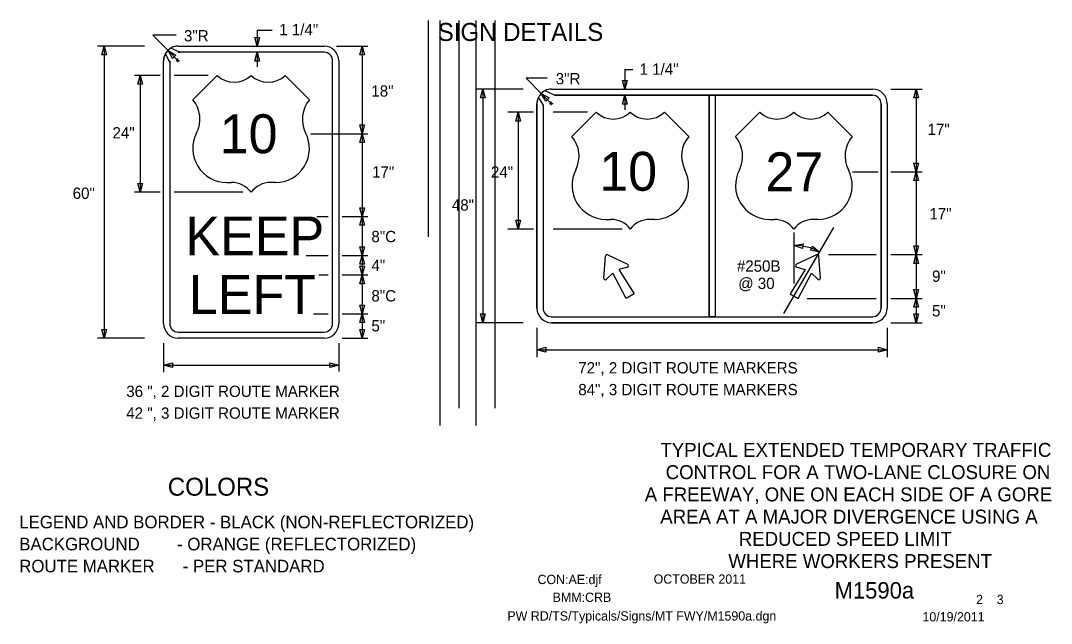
# Model space of a CAD drawing. Extents: x 16728 to 19504, y 5553 to 7079.
# Drawn here: x 17774 to 18463, y 5932 to 6334 of the extents above; entities that cross this region are included whole.
import ezdxf

# ---------------------------------------------------------------- set-up
doc = ezdxf.new("R2010")
doc.units = 0
for name, color, linetype in [('ALI_LEGAL_EX', 7, 'Continuous'), ('BORDER', 7, 'Continuous'), ('BORDER_SIGNAL_WO', 7, 'Continuous'), ('TRAFFIC_SIGNS_PR', 7, 'Continuous'), ('TYPICAL_EX', 7, 'Continuous'), ('TYPICAL_TEXT_DIMEN_PR', 7, 'Continuous')]:
    doc.layers.add(name, color=color, linetype=linetype)

msp = doc.modelspace()

# ---------------------------------------------------------------- linework, layer by layer
at = {"layer": 'ALI_LEGAL_EX'}
for p, q in [((18046.81, 6189.84), (18046.81, 6334.29)), ((18054.48, 6334.29), (18054.48, 6206.79)), ((18054.48, 6334.29), (18054.48, 6063.94)), ((18067.45, 6075.61), (18067.45, 6334.29)), ((18078.48, 6334.29), (18078.48, 6206.79)), ((18078.48, 6334.29), (18078.48, 6063.94)), ((18091.45, 6075.61), (18091.45, 6334.29))]:
    msp.add_line(p, q, dxfattribs=at)
at = {"layer": 'TRAFFIC_SIGNS_PR'}
for p, q in [((17879.58, 6317.25), (17977.08, 6317.25)), ((17872, 6313.63), (17870.99, 6312.12)), ((17871.02, 6312.05), (17873.89, 6306.01)), ((17880.78, 6313.18), (17874.69, 6315.93)), ((17977.08, 6313.18), (17879.58, 6313.18)), ((17869.83, 6132), (17869.83, 6307.5)), ((17873.89, 6307.5), (17873.89, 6132)), ((17982.77, 6132), (17982.77, 6307.5)), ((17986.83, 6307.5), (17986.83, 6132)), ((18120.27, 6282.81), (18123.41, 6277.76)), ((18131.06, 6284.5), (18124.82, 6287.51)), ((18129.1, 6288.55), (18343.6, 6288.55)), ((18129.1, 6288.55), (18343.6, 6288.55)), ((18131.04, 6284.49), (18234.32, 6284.49)), ((18343.6, 6284.49), (18131.04, 6284.49)), ((18234.32, 6284.49), (18234.32, 6136.61)), ((18238.38, 6284.49), (18238.38, 6136.61)), ((18238.38, 6284.49), (18343.6, 6284.49)), ((18119.35, 6278.8), (18119.35, 6142.3)), ((18119.35, 6142.3), (18119.35, 6278.8)), ((18123.41, 6277.75), (18123.41, 6142.3)), ((18123.41, 6277.75), (18123.41, 6142.3)), ((18349.29, 6278.8), (18349.29, 6233.05)), ((18349.29, 6142.3), (18349.29, 6278.8)), ((18353.35, 6278.8), (18353.35, 6142.3)), ((18353.35, 6278.8), (18353.35, 6142.3)), ((18349.29, 6233.05), (18349.29, 6142.3)), ((18163.95, 6162.41), (18165.1, 6177.12)), ((18166.62, 6177.99), (18179.93, 6171.63)), ((18306.08, 6177.99), (18292.77, 6171.63)), ((18308.75, 6162.41), (18307.6, 6177.12)), ((18129.1, 6136.61), (18343.6, 6136.61)), ((18129.1, 6132.55), (18343.6, 6132.55)), ((18343.6, 6132.55), (18129.1, 6132.55)), ((17879.58, 6126.31), (17977.08, 6126.31)), ((17977.08, 6122.25), (17879.58, 6122.25))]:
    msp.add_line(p, q, dxfattribs=at)
for points in [[(18131.04, 6284.49), (18131.03, 6284.49)], [(18123.41, 6277.76), (18123.41, 6277.75)], [(18179.77, 6169.66), (18174.04, 6168.09), (18184.26, 6151.92), (18178.86, 6148.8), (18169.97, 6165.74), (18165.74, 6161.57)], [(18292.93, 6169.66), (18298.66, 6168.09), (18288.44, 6151.92), (18293.84, 6148.8), (18302.73, 6165.74), (18306.96, 6161.57)]]:
    msp.add_lwpolyline(points, dxfattribs=at)
msp.add_lwpolyline([(18234.32, 6284.49), (18238.38, 6284.49), (18238.38, 6136.61), (18234.32, 6136.61)], close=True, dxfattribs=at)
for centre, radius, start, end in [((17879.58, 6307.5), 9.75, 90, 180), ((17878.99, 6309.67), 7.6, 85.58319, 124.53531), ((17977.08, 6307.5), 9.75, 0, 90), ((17876.86, 6308.09), 7.06, 145.86811, 184.82317), ((17880.18, 6317.61), 4.47, 262.2432, 277.7568), ((17977.08, 6307.5), 5.69, 0, 90), ((17868.43, 6306.75), 5.51, 352.24294, 7.75653), ((18125.48, 6279.5), 6.17, 147.60925, 186.56283), ((18129.1, 6278.8), 9.75, 90, 180), ((18129.1, 6278.8), 9.75, 90, 180), ((18128.42, 6281.98), 6.6, 84.11162, 123.06374), ((18130.04, 6291.67), 7.24, 277.81035, 278.05403), ((18343.6, 6278.8), 9.75, 0, 90), ((18343.6, 6278.8), 9.75, 0, 90), ((18343.6, 6278.8), 5.69, 0, 89.99421), ((18343.6, 6278.8), 5.69, 0, 90), ((18166.16, 6177.04), 1.06, 64.48226, 175.51774), ((18306.54, 6177.04), 1.06, 4.48226, 115.51774), ((18179.47, 6170.68), 1.06, 285.9885, 64.48226), ((18293.23, 6170.68), 1.06, 115.51774, 254.0115), ((18165.01, 6162.33), 1.06, 175.51775, 314.01151), ((18307.69, 6162.33), 1.06, 225.98849, 4.48225), ((18129.1, 6142.3), 9.75, 180, 270), ((18129.1, 6142.3), 9.75, 180, 270), ((18129.1, 6142.3), 5.69, 180, 270), ((18129.1, 6142.3), 5.69, 180, 270), ((18343.6, 6142.3), 9.75, 270, 0), ((18343.6, 6142.3), 5.69, 270, 0), ((18343.6, 6142.3), 9.75, 270, 0), ((18343.6, 6142.3), 5.69, 270, 0), ((17879.58, 6132), 9.75, 180, 270), ((17879.58, 6132), 5.69, 180, 270), ((17977.08, 6132), 5.69, 270, 0), ((17977.08, 6132), 9.75, 270, 0)]:
    msp.add_arc(centre, radius, start, end, dxfattribs=at)
at = {"layer": 'TYPICAL_EX'}
for p, q in [((17889.33, 6281.5), (17905.58, 6297.75)), ((17967.33, 6281.5), (17951.08, 6297.75)), ((18142.71, 6256.89), (18158.96, 6273.14)), ((18220.71, 6256.89), (18204.46, 6273.14)), ((18251.99, 6256.89), (18268.24, 6273.14)), ((18329.99, 6256.89), (18313.74, 6273.14)), ((17912.06, 6226.21), (17915.31, 6226.21)), ((17944.6, 6226.21), (17941.35, 6226.21)), ((18165.44, 6201.6), (18168.69, 6201.6)), ((18197.98, 6201.6), (18194.73, 6201.6)), ((18274.72, 6201.6), (18277.97, 6201.6)), ((18307.26, 6201.6), (18304.01, 6201.6))]:
    msp.add_line(p, q, dxfattribs=at)
for centre, radius, start, end in [((17916.95, 6309.58), 16.42, 226.14041, 313.85958), ((17939.7, 6309.59), 16.42, 226.14042, 313.85959), ((17873.93, 6268.49), 20.16, 333.09768, 40.19361), ((17982.73, 6268.49), 20.16, 139.80639, 206.90233), ((18170.34, 6284.97), 16.42, 226.14041, 313.85958), ((18193.09, 6284.97), 16.42, 226.14042, 313.85959), ((18279.62, 6284.97), 16.42, 226.14041, 313.85958), ((18302.36, 6284.97), 16.42, 226.14042, 313.85959), ((17912.1, 6248.93), 22.73, 152.6698, 269.90132), ((17944.56, 6248.93), 22.73, 270.09868, 27.3302), ((18127.31, 6243.88), 20.16, 333.09768, 40.19361), ((18236.11, 6243.88), 20.16, 139.80639, 206.90233), ((18236.59, 6243.88), 20.16, 333.09768, 40.19361), ((18345.39, 6243.88), 20.16, 139.80639, 206.90233), ((18165.48, 6224.32), 22.73, 152.6698, 269.90132), ((18197.94, 6224.32), 22.73, 270.09868, 27.3302), ((18274.76, 6224.32), 22.73, 152.6698, 269.90132), ((18307.22, 6224.32), 22.73, 270.09868, 27.3302), ((17915.35, 6209.93), 16.28, 37.1038, 90.13853), ((17941.31, 6209.93), 16.28, 89.86147, 142.8962), ((18168.73, 6185.32), 16.28, 37.1038, 90.13853), ((18194.69, 6185.32), 16.28, 89.86147, 142.8962), ((18278.01, 6185.32), 16.28, 37.1038, 90.13853), ((18303.97, 6185.32), 16.28, 89.86147, 142.8962)]:
    msp.add_arc(centre, radius, start, end, dxfattribs=at)
at = {"layer": 'TYPICAL_TEXT_DIMEN_PR'}
for p, q in [((17878.2, 6324.53), (17862.54, 6324.53)), ((17862.54, 6324.53), (17872.78, 6314.29)), ((17932.3, 6328.01), (17932.3, 6317.25)), ((17932.3, 6328.01), (17942.41, 6328.01)), ((17857, 6317.25), (17825.71, 6317.25)), ((17828.47, 6311.38), (17830.04, 6317.25)), ((17830.04, 6317.25), (17830.04, 6122.25)), ((17830.04, 6317.25), (17831.62, 6311.38)), ((17932.3, 6317.25), (17930.73, 6323.11)), ((17930.73, 6323.11), (17932.3, 6323.11)), ((17932.3, 6323.11), (17933.87, 6323.11)), ((17933.87, 6323.11), (17932.3, 6317.25)), ((17985.37, 6317.25), (18006.33, 6317.25)), ((18000.86, 6311.38), (18002.43, 6317.25)), ((18002.43, 6317.25), (18002.43, 6258.75)), ((18002.43, 6317.25), (18004, 6311.38)), ((17830.04, 6311.38), (17828.47, 6311.38)), ((17831.62, 6311.38), (17830.04, 6311.38)), ((17872.78, 6314.29), (17879.34, 6307.74)), ((17875.81, 6309.04), (17872.78, 6314.29)), ((17872.78, 6314.29), (17878.04, 6311.26)), ((17876.92, 6310.15), (17875.81, 6309.04)), ((17878.04, 6311.26), (17876.92, 6310.15)), ((17930.78, 6307.32), (17932.35, 6313.18)), ((17932.35, 6313.18), (17932.35, 6303.43)), ((17932.35, 6313.18), (17933.92, 6307.32)), ((18002.43, 6311.38), (18000.86, 6311.38)), ((18004, 6311.38), (18002.43, 6311.38)), ((17878.13, 6307.74), (17880.55, 6307.74)), ((17879.34, 6306.53), (17879.34, 6308.95)), ((17932.35, 6307.32), (17930.78, 6307.32)), ((17933.92, 6307.32), (17932.35, 6307.32)), ((17867.46, 6297.75), (17850.33, 6297.75)), ((17852.65, 6291.88), (17854.23, 6297.75)), ((17854.23, 6297.75), (17854.23, 6219.75)), ((17854.23, 6297.75), (17855.8, 6291.88)), ((17899.7, 6297.75), (17876.82, 6297.75)), ((18126.24, 6295.83), (18112.06, 6295.83)), ((18112.06, 6295.83), (18122.21, 6285.69)), ((18177.96, 6301.7), (18177.96, 6288.55)), ((18177.96, 6301.7), (18183.48, 6301.7)), ((17854.23, 6291.88), (17852.65, 6291.88)), ((17855.8, 6291.88), (17854.23, 6291.88)), ((18177.96, 6288.55), (18176.39, 6294.41)), ((18176.39, 6294.41), (18177.96, 6294.41)), ((18177.96, 6294.41), (18179.53, 6294.41)), ((18179.53, 6294.41), (18177.96, 6288.55)), ((18110.12, 6288.55), (18078.82, 6288.55)), ((18081.59, 6282.69), (18083.16, 6288.55)), ((18083.16, 6282.69), (18081.59, 6282.69)), ((18083.16, 6288.55), (18083.16, 6132.55)), ((18083.16, 6288.55), (18084.73, 6282.69)), ((18084.73, 6282.69), (18083.16, 6282.69)), ((18122.21, 6285.69), (18128.86, 6279.04)), ((18125.25, 6280.43), (18122.21, 6285.68)), ((18122.21, 6285.68), (18127.47, 6282.65)), ((18127.47, 6282.65), (18126.36, 6281.54)), ((18176.44, 6278.62), (18178.01, 6284.49)), ((18176.44, 6278.62), (18178.01, 6284.49)), ((18178.01, 6284.49), (18178.01, 6274.74)), ((18178.01, 6284.49), (18179.58, 6278.62)), ((18178.01, 6284.49), (18179.58, 6278.62)), ((18355.72, 6288.55), (18376.68, 6288.55)), ((18371.22, 6282.69), (18372.79, 6288.55)), ((18372.79, 6282.69), (18371.22, 6282.69)), ((18372.78, 6288.55), (18372.78, 6233.3)), ((18372.79, 6288.55), (18374.36, 6282.69)), ((18374.36, 6282.69), (18372.79, 6282.69)), ((18126.36, 6281.54), (18125.25, 6280.43)), ((18127.65, 6279.04), (18130.07, 6279.04)), ((18128.86, 6277.83), (18128.86, 6280.25)), ((18178.01, 6278.62), (18176.44, 6278.62)), ((18178.01, 6278.62), (18176.44, 6278.62)), ((18179.58, 6278.62), (18178.01, 6278.62)), ((18179.58, 6278.62), (18178.01, 6278.62)), ((18116.98, 6273.14), (18099.85, 6273.14)), ((18105.15, 6267.27), (18106.72, 6273.14)), ((18106.72, 6273.14), (18106.72, 6195.14)), ((18106.72, 6273.14), (18108.29, 6267.27)), ((18153.08, 6273.14), (18130.2, 6273.14)), ((18002.43, 6258.75), (18000.86, 6264.61)), ((18000.86, 6264.61), (18002.43, 6264.61)), ((18002.43, 6264.61), (18004, 6264.61)), ((18004, 6264.61), (18002.43, 6258.75)), ((18106.72, 6267.27), (18105.15, 6267.27)), ((18108.29, 6267.27), (18106.72, 6267.27)), ((17968.22, 6258.75), (18006.33, 6258.75)), ((18000.86, 6252.88), (18002.43, 6258.75)), ((18002.43, 6258.75), (18002.43, 6203.5)), ((18002.43, 6258.75), (18004, 6252.88)), ((18002.43, 6252.88), (18000.86, 6252.88)), ((18004, 6252.88), (18002.43, 6252.88)), ((18372.79, 6233.3), (18371.22, 6239.16)), ((18371.22, 6239.16), (18372.79, 6239.16)), ((18372.79, 6239.16), (18374.36, 6239.16)), ((18374.36, 6239.16), (18372.79, 6233.3)), ((18330.17, 6233.3), (18347.32, 6233.3)), ((18355.72, 6233.3), (18376.68, 6233.3)), ((18371.22, 6227.44), (18372.79, 6233.3)), ((18372.79, 6227.44), (18371.22, 6227.44)), ((18372.78, 6233.3), (18372.78, 6178.05)), ((18372.79, 6233.3), (18374.36, 6227.44)), ((18374.36, 6227.44), (18372.79, 6227.44)), ((17854.23, 6219.75), (17852.65, 6225.61)), ((17852.65, 6225.61), (17854.23, 6225.61)), ((17854.23, 6225.61), (17855.8, 6225.61)), ((17855.8, 6225.61), (17854.23, 6219.75)), ((17867.46, 6219.75), (17850.33, 6219.75)), ((17922.82, 6219.75), (17876.82, 6219.75)), ((18002.43, 6203.5), (18000.86, 6209.36)), ((18000.86, 6209.36), (18002.43, 6209.36)), ((18002.43, 6209.36), (18004, 6209.36)), ((18004, 6209.36), (18002.43, 6203.5)), ((17972.16, 6203.5), (17979.84, 6203.5)), ((17989.2, 6203.5), (18006.33, 6203.5)), ((18000.86, 6197.63), (18002.43, 6203.5)), ((18002.43, 6203.5), (18002.43, 6177.5)), ((18002.43, 6203.5), (18004, 6197.63)), ((18106.72, 6195.14), (18105.15, 6201)), ((18105.15, 6201), (18106.72, 6201)), ((18106.72, 6201), (18108.29, 6201)), ((18108.29, 6201), (18106.72, 6195.14)), ((18002.43, 6197.63), (18000.86, 6197.63)), ((18004, 6197.63), (18002.43, 6197.63)), ((18116.98, 6195.14), (18099.85, 6195.14)), ((18176.2, 6195.14), (18130.2, 6195.14)), ((18284.38, 6138.65), (18317.62, 6196.24)), ((18291.14, 6158.8), (18291.14, 6192.8)), ((18002.43, 6177.5), (18000.86, 6183.36)), ((18000.86, 6183.36), (18002.43, 6183.36)), ((18002.43, 6183.36), (18004, 6183.36)), ((18004, 6183.36), (18002.43, 6177.5)), ((18291.17, 6184.24), (18297.16, 6185.2)), ((18296.84, 6182.08), (18291.17, 6184.24)), ((18297, 6183.64), (18296.84, 6182.08)), ((18297.16, 6185.2), (18297, 6183.64)), ((18302.15, 6180.92), (18302.84, 6182.33)), ((18308.12, 6179.79), (18302.15, 6180.92)), ((18302.84, 6182.33), (18303.52, 6183.75)), ((18303.52, 6183.75), (18308.12, 6179.79)), ((18372.79, 6178.05), (18371.22, 6183.91)), ((18371.22, 6183.91), (18372.79, 6183.91)), ((18372.79, 6183.91), (18374.36, 6183.91)), ((18374.36, 6183.91), (18372.79, 6178.05)), ((17965.14, 6177.5), (17979.84, 6177.5)), ((17989.2, 6177.5), (18006.33, 6177.5)), ((18000.86, 6171.63), (18002.43, 6177.5)), ((18002.43, 6177.5), (18002.43, 6164.5)), ((18002.43, 6177.5), (18004, 6171.63)), ((18314.09, 6178.05), (18345.96, 6178.05)), ((18355.72, 6178.05), (18376.68, 6178.05)), ((18371.22, 6172.19), (18372.79, 6178.05)), ((18372.79, 6172.19), (18371.22, 6172.19)), ((18372.78, 6178.05), (18372.78, 6148.8)), ((18372.79, 6178.05), (18374.36, 6172.19)), ((18374.36, 6172.19), (18372.79, 6172.19)), ((18002.43, 6171.63), (18000.86, 6171.63)), ((18002.43, 6164.5), (18000.86, 6170.36)), ((18000.86, 6170.36), (18002.43, 6170.36)), ((18004, 6171.63), (18002.43, 6171.63)), ((18002.43, 6170.36), (18004, 6170.36)), ((18004, 6170.36), (18002.43, 6164.5)), ((17973.49, 6164.5), (17979.84, 6164.5)), ((17989.2, 6164.5), (18006.33, 6164.5)), ((18000.86, 6158.63), (18002.43, 6164.5)), ((18002.43, 6158.63), (18000.86, 6158.63)), ((18002.43, 6164.5), (18002.43, 6138.5)), ((18002.43, 6164.5), (18004, 6158.63)), ((18004, 6158.63), (18002.43, 6158.63)), ((18372.79, 6148.8), (18371.22, 6154.66)), ((18371.22, 6154.66), (18372.79, 6154.66)), ((18372.79, 6154.66), (18374.36, 6154.66)), ((18374.36, 6154.66), (18372.79, 6148.8)), ((18002.43, 6138.5), (18000.86, 6144.36)), ((18000.86, 6144.36), (18002.43, 6144.36)), ((18002.43, 6144.36), (18004, 6144.36)), ((18004, 6144.36), (18002.43, 6138.5)), ((18299.96, 6148.8), (18345.96, 6148.8)), ((18355.72, 6148.8), (18376.68, 6148.8)), ((18371.22, 6142.94), (18372.79, 6148.8)), ((18372.78, 6148.8), (18372.78, 6132.55)), ((18372.79, 6148.8), (18374.36, 6142.94)), ((17969.99, 6138.5), (17979.84, 6138.5)), ((17989.2, 6138.5), (18006.33, 6138.5)), ((18000.86, 6132.63), (18002.43, 6138.5)), ((18002.43, 6138.5), (18002.43, 6122.25)), ((18002.43, 6138.5), (18004, 6132.63)), ((18083.16, 6132.55), (18081.59, 6138.41)), ((18081.59, 6138.41), (18083.16, 6138.41)), ((18083.16, 6138.41), (18084.73, 6138.41)), ((18084.73, 6138.41), (18083.16, 6132.55)), ((18372.79, 6142.94), (18371.22, 6142.94)), ((18372.79, 6132.55), (18371.22, 6138.41)), ((18371.22, 6138.41), (18372.79, 6138.41)), ((18374.36, 6142.94), (18372.79, 6142.94)), ((18372.79, 6138.41), (18374.36, 6138.41)), ((18374.36, 6138.41), (18372.79, 6132.55)), ((18002.43, 6132.63), (18000.86, 6132.63)), ((18004, 6132.63), (18002.43, 6132.63)), ((18110.12, 6132.55), (18078.82, 6132.55)), ((18355.72, 6132.55), (18372.85, 6132.55)), ((18355.72, 6132.55), (18376.68, 6132.55)), ((18355.72, 6132.55), (18372.85, 6132.55)), ((17830.04, 6122.25), (17828.47, 6128.11)), ((17828.47, 6128.11), (17830.04, 6128.11)), ((17830.04, 6128.11), (17831.62, 6128.11)), ((17831.62, 6128.11), (17830.04, 6122.25)), ((18002.43, 6122.25), (18000.86, 6128.11)), ((18000.86, 6128.11), (18002.43, 6128.11)), ((18002.43, 6128.11), (18004, 6128.11)), ((18004, 6128.11), (18002.43, 6122.25)), ((18119.35, 6129.2), (18119.35, 6109.64)), ((18353.35, 6129.2), (18353.35, 6109.64)), ((17857, 6122.25), (17825.71, 6122.25)), ((17869.83, 6118.9), (17869.83, 6099.55)), ((17986.83, 6118.9), (17986.83, 6100.01)), ((17989.2, 6122.25), (18006.33, 6122.25)), ((18119.35, 6114.58), (18125.21, 6116.15)), ((18119.35, 6114.58), (18353.35, 6114.58)), ((18125.21, 6113.01), (18119.35, 6114.58)), ((18125.21, 6116.15), (18125.21, 6114.58)), ((18125.21, 6114.58), (18125.21, 6113.01)), ((18347.49, 6114.58), (18347.49, 6116.15)), ((18347.49, 6116.15), (18353.35, 6114.58)), ((18353.35, 6114.58), (18347.49, 6113.01)), ((18347.49, 6113.01), (18347.49, 6114.58)), ((17869.83, 6104.27), (17875.69, 6105.85)), ((17869.83, 6104.27), (17986.83, 6104.27)), ((17875.69, 6102.7), (17869.83, 6104.27)), ((17875.69, 6105.85), (17875.69, 6104.27)), ((17875.69, 6104.27), (17875.69, 6102.7)), ((17980.97, 6104.27), (17980.97, 6105.85)), ((17980.97, 6105.85), (17986.83, 6104.27)), ((17986.83, 6104.27), (17980.97, 6102.7)), ((17980.97, 6102.7), (17980.97, 6104.27))]:
    msp.add_line(p, q, dxfattribs=at)
msp.add_arc((18291.33, 6149.8), 34.39, 60.74521, 90.32117, dxfattribs=at)

# ---------------------------------------------------------------- texts
at = {"layer": 'BORDER'}
for s, p in [('TYPICAL EXTENDED TEMPORARY TRAFFIC', (18201.85, 6043.01)), ('CONTROL FOR A TWO-LANE CLOSURE ON', (18205.35, 6028.16)), ('A FREEWAY, ONE ON EACH SIDE OF A GORE', (18191.37, 6013.31)), ('AREA AT A MAJOR DIVERGENCE USING A', (18201.72, 5998.46)), ('REDUCED SPEED LIMIT', (18254.22, 5983.61)), ('WHERE WORKERS PRESENT', (18247.22, 5968.76))]:
    msp.add_text(s, height=9.3, dxfattribs=at).set_placement(p)
at = {"layer": 'BORDER_SIGNAL_WO'}
for s, height, p in [('CON:AE:djf  ', 6.2, (18119.69, 5958.06)), ('    OCTOBER 2011    ', 6.2, (18188.08, 5958.34)), ('    M1590a   ', 11, (18301.86, 5948.38)), ('BMM:CRB   ', 6.2, (18129.81, 5946.17)), (' 2    3 ', 6.2, (18410.45, 5944.7)), ('PW RD/TS/Typicals/Signs/MT FWY/M1590a.dgn      ', 6.2, (18099.55, 5933.71)), ('10/19/2011    ', 6.2, (18376.93, 5933.13))]:
    msp.add_text(s, height=height, dxfattribs=at).set_placement(p)
at = {"layer": 'TRAFFIC_SIGNS_PR'}
for s, p in [('10', (17907.3, 6245.75)), ('10', (18160.95, 6220.68)), ('27', (18271.96, 6220.32)), ('KEEP', (17884.43, 6177.5)), ('LEFT', (17886.67, 6138.5))]:
    msp.add_text(s, height=26, dxfattribs=at).set_placement(p)
at = {"layer": 'TYPICAL_TEXT_DIMEN_PR'}
for s, height, p in [('1 1/4"', 7.55, (17947.1, 6324.5)), ('SIGN DETAILS', 12, (18053.06, 6320.72)), ('3"R', 7.55, (17883.47, 6320.41)), ('1 1/4"', 7.55, (18187.89, 6298.12)), ('3"R', 7.55, (18131.88, 6291.75)), ('18"', 7.55, (18008.67, 6283.52)), ('24"', 7.55, (17835.67, 6255.63)), ('17"', 7.55, (18380.36, 6257.91)), ('17"', 7.55, (18009.13, 6229.47)), ('24"', 7.55, (18088.58, 6229.47)), ('60"', 7.55, (17809.07, 6215.26)), ('48"', 7.55, (18062.46, 6207.45)), ('17"', 7.55, (18381.56, 6201.55)), ('8"C', 7.55, (18008.71, 6186.35)), ('4" ', 7.55, (18008.71, 6167.09)), ('#250B', 7.55, (18252.91, 6166.64)), ('9"', 7.55, (18383.34, 6159.89)), ('@ 30', 7.55, (18253.86, 6155.09)), ('8"C', 7.55, (18008.71, 6146.77)), ('5"', 7.55, (18383.34, 6136.79)), ('5" ', 7.55, (18008.71, 6126.79)), ('72", 2 DIGIT ROUTE MARKERS', 7.55, (18146.93, 6098.71)), ('36 ", 2 DIGIT ROUTE MARKER', 7.55, (17844.88, 6083.01)), ('84", 3 DIGIT ROUTE MARKERS', 7.55, (18146.93, 6084.16)), ('42 ", 3 DIGIT ROUTE MARKER', 7.55, (17844.88, 6068.47)), ('COLORS', 12, (17872.65, 6017.08)), ('LEGEND AND BORDER - BLACK (NON-REFLECTORIZED)', 8.4, (17773.37, 5995.3)), ('BACKGROUND        - ORANGE (REFLECTORIZED)', 8.4, (17773.37, 5980.6)), ('ROUTE MARKER      - PER STANDARD', 8.4, (17773.37, 5965.9))]:
    msp.add_text(s, height=height, dxfattribs=at).set_placement(p)

doc.saveas('drawing.dxf')
